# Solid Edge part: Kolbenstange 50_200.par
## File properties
Username: ahadarics
Dokumentum tartalom típus: 0
Author: ahadarics
Last saved by: ahadarics
Revision: 85
Sűrűség: 0,000 kg/m^3
Pontosság: 0,990
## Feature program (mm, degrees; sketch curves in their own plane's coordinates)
base feature "unnamed BaseFeature 1"
thread "unnamed Thread 1"
chamfer "Letörés_1"  SetBackValue2 = 20 deg
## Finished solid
Body 1: solid body, 21 faces, 32 edges, 14 vertices.
  Faces by surface: plane 8, cylinder 5, cone 4, torus 4
  Edges by curve: circle 17, line 9, curve on surface 4, ellipse 2
Bounding box of the edges (mm; curved faces can reach further): 50.000 x 50.000 x 344.000, from (-25, -25, -86.5) to (25, 25, 257.5).
Cylindrical faces by radius (mm): R6.75 x1, R8 x1, R9.75 x1, R10 x1, R25 x1
Conical faces (half-angle, radius in mm at the cone's reference point): 20 deg R8 x1, 30 deg R9.875 x1, 45 deg R24.25 x1, 60 deg R7.375 x1
Toroidal faces (ring radius, tube radius in mm): R7.15 r0.4 x2, R8.55 r1.2 x2
Planar faces by outward normal: +x 1, +z 3, -x 1, -z 1, oblique 2
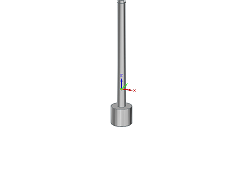
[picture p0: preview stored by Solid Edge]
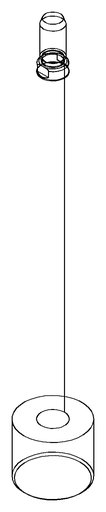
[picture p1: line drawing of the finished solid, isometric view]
